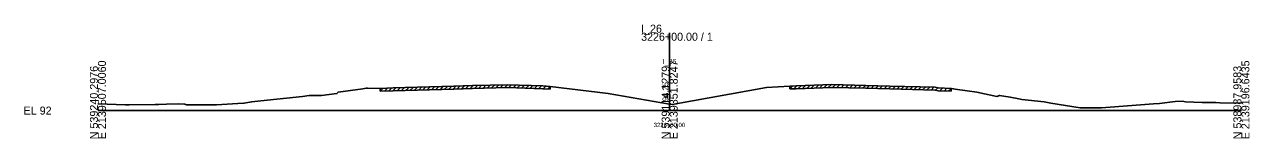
# Model space of a CAD drawing. Extents: x -13101 to 4803, y -924 to 22390.
# Drawn here: x 1974.3 to 2402.8, y 12990.3 to 13030 of the extents above; entities that cross this region are included whole.
import ezdxf

# ---------------------------------------------------------------- set-up
doc = ezdxf.new("R2010")
doc.units = 0
for name, color, linetype in [('RD_GPK_XS_Cell', 7, 'Continuous'), ('RD_XS_ExGround', 7, 'Continuous'), ('RD_XS_ExPaveRet', 7, 'Continuous'), ('RD_XS_TX_Baseline', 7, 'Continuous'), ('RD_XS_TX_Elev_EX', 7, 'Continuous'), ('RD_XS_TX_Station', 7, 'Continuous')]:
    doc.layers.add(name, color=color, linetype=linetype)

msp = doc.modelspace()

# ---------------------------------------------------------------- linework, layer by layer
at = {"layer": 'RD_GPK_XS_Cell'}
for p, q in [((2200, 13000), (2200, 13027.15)), ((2000, 13000), (2200, 13000)), ((2200, 13000), (2400, 13000))]:
    msp.add_line(p, q, dxfattribs=at)
at = {"layer": 'RD_XS_ExGround'}
msp.add_lwpolyline([(2000, 13002.32), (2009.65, 13002.05), (2010.92, 13002.01), (2020.04, 13002.16), (2020.93, 13002.16), (2021.28, 13002.17), (2024, 13002.29), (2028.09, 13002.33), (2030.37, 13002.27), (2030.93, 13002.04), (2031.49, 13002.03), (2040.94, 13002.07), (2041.47, 13002.06), (2048.99, 13002.46), (2051.05, 13002.58), (2053.82, 13003.06), (2056.98, 13003.41), (2071.61, 13004.96), (2073.84, 13005.24), (2076.21, 13005.22), (2078.21, 13005.25), (2083.62, 13005.96), (2083.99, 13006.45), (2092.65, 13007.57), (2093.86, 13007.82), (2094.26, 13007.81), (2098.71, 13007.75), (2103.22, 13007.9), (2124.54, 13008.53), (2131, 13008.75), (2143.23, 13009.02), (2155.69, 13008.62), (2158.15, 13008.46), (2178.43, 13006.02), (2200, 13002.25), (2200.9, 13002.1), (2233.82, 13008.05), (2241.98, 13008.54), (2244.21, 13008.63), (2256.7, 13009.05), (2268.68, 13008.78), (2277.02, 13008.54), (2292.83, 13008.13), (2293.92, 13007.89), (2298.53, 13007.74), (2299.19, 13007.63), (2299.88, 13007.51), (2304.06, 13006.85), (2307.51, 13006.38), (2314.48, 13004.97), (2315.4, 13005.32), (2319.09, 13004.65), (2322.18, 13004.05), (2322.74, 13003.95), (2323.14, 13003.9), (2331.05, 13003.05), (2333.39, 13002.6), (2343.61, 13001.02), (2345.05, 13001.01), (2351.06, 13000.99), (2369.27, 13002.32), (2371.33, 13002.48), (2376.84, 13003.18), (2379.31, 13003.29), (2380.48, 13003.08), (2386.33, 13002.87), (2391.08, 13002.77), (2392.48, 13002.68), (2400, 13002.59)], dxfattribs=at)
at = {"layer": 'RD_XS_ExPaveRet'}
for p, q in [((2098.71, 13006.75), (2099.74, 13007.79)), ((2098.71, 13006.75), (2098.71, 13007.75)), ((2098.71, 13006.75), (2103.22, 13006.9)), ((2100.21, 13006.8), (2101.24, 13007.83)), ((2101.71, 13006.85), (2102.74, 13007.88)), ((2103.21, 13006.9), (2104.24, 13007.93)), ((2103.22, 13006.9), (2124.54, 13007.53)), ((2104.71, 13006.94), (2105.74, 13007.97)), ((2106.21, 13006.99), (2107.24, 13008.02)), ((2107.71, 13007.03), (2108.74, 13008.06)), ((2109.21, 13007.07), (2110.24, 13008.11)), ((2110.71, 13007.12), (2111.74, 13008.15)), ((2112.21, 13007.16), (2113.24, 13008.19)), ((2113.71, 13007.21), (2114.74, 13008.24)), ((2115.21, 13007.25), (2116.24, 13008.28)), ((2116.71, 13007.3), (2117.74, 13008.33)), ((2118.21, 13007.34), (2119.24, 13008.37)), ((2119.71, 13007.38), (2120.74, 13008.41)), ((2121.21, 13007.43), (2122.24, 13008.46)), ((2122.71, 13007.47), (2123.74, 13008.5)), ((2124.21, 13007.52), (2125.24, 13008.55)), ((2124.54, 13007.53), (2131, 13007.75)), ((2125.71, 13007.57), (2126.74, 13008.6)), ((2127.21, 13007.62), (2128.24, 13008.65)), ((2128.71, 13007.67), (2129.74, 13008.7)), ((2130.21, 13007.72), (2131.24, 13008.75)), ((2131, 13007.75), (2143.23, 13008.02)), ((2131.71, 13007.76), (2132.73, 13008.79)), ((2133.21, 13007.8), (2134.23, 13008.82)), ((2134.71, 13007.83), (2135.73, 13008.85)), ((2136.21, 13007.86), (2137.23, 13008.88)), ((2137.71, 13007.89), (2138.73, 13008.92)), ((2139.21, 13007.93), (2140.23, 13008.95)), ((2140.71, 13007.96), (2141.73, 13008.98)), ((2142.21, 13007.99), (2143.23, 13009.02)), ((2143.23, 13008.02), (2155.69, 13007.62)), ((2143.71, 13008), (2144.68, 13008.97)), ((2145.21, 13007.95), (2146.18, 13008.92)), ((2146.71, 13007.91), (2147.68, 13008.88)), ((2148.21, 13007.86), (2149.18, 13008.83)), ((2149.71, 13007.81), (2150.68, 13008.78)), ((2151.21, 13007.77), (2152.18, 13008.73)), ((2152.71, 13007.72), (2153.68, 13008.69)), ((2154.21, 13007.67), (2155.18, 13008.64)), ((2155.69, 13007.62), (2158.15, 13007.46)), ((2155.71, 13007.62), (2156.64, 13008.56)), ((2157.21, 13007.52), (2158.14, 13008.46)), ((2158.15, 13008.46), (2158.15, 13007.46)), ((2241.98, 13007.54), (2243.03, 13008.58)), ((2241.98, 13007.54), (2241.98, 13008.54)), ((2241.98, 13007.54), (2244.21, 13007.63)), ((2243.48, 13007.6), (2244.53, 13008.65)), ((2244.21, 13007.63), (2256.7, 13008.05)), ((2244.98, 13007.66), (2246.02, 13008.69)), ((2246.48, 13007.71), (2247.52, 13008.74)), ((2247.98, 13007.76), (2249.02, 13008.79)), ((2249.48, 13007.81), (2250.52, 13008.84)), ((2250.98, 13007.86), (2252.02, 13008.89)), ((2252.48, 13007.91), (2253.52, 13008.94)), ((2253.98, 13007.96), (2255.02, 13008.99)), ((2255.48, 13008.01), (2256.52, 13009.04)), ((2256.7, 13008.05), (2268.68, 13007.78)), ((2256.98, 13008.04), (2257.96, 13009.02)), ((2258.48, 13008.01), (2259.46, 13008.99)), ((2259.98, 13007.98), (2260.96, 13008.95)), ((2261.48, 13007.94), (2262.46, 13008.92)), ((2262.98, 13007.91), (2263.96, 13008.89)), ((2264.48, 13007.88), (2265.46, 13008.85)), ((2265.98, 13007.84), (2266.96, 13008.82)), ((2267.48, 13007.81), (2268.46, 13008.79)), ((2268.68, 13007.78), (2277.02, 13007.54)), ((2268.98, 13007.77), (2269.96, 13008.75)), ((2270.48, 13007.73), (2271.46, 13008.7)), ((2271.98, 13007.69), (2272.96, 13008.66)), ((2273.48, 13007.65), (2274.46, 13008.62)), ((2274.98, 13007.6), (2275.96, 13008.57)), ((2276.48, 13007.56), (2277.46, 13008.53)), ((2277.02, 13007.54), (2292.83, 13007.13)), ((2277.98, 13007.52), (2278.96, 13008.49)), ((2279.48, 13007.48), (2280.46, 13008.46)), ((2280.98, 13007.44), (2281.96, 13008.42)), ((2282.48, 13007.4), (2283.46, 13008.38)), ((2283.98, 13007.36), (2284.96, 13008.34)), ((2285.48, 13007.33), (2286.46, 13008.3)), ((2286.98, 13007.29), (2287.96, 13008.26)), ((2288.48, 13007.25), (2289.46, 13008.22)), ((2289.98, 13007.21), (2290.96, 13008.18)), ((2291.48, 13007.17), (2292.46, 13008.14)), ((2292.83, 13007.13), (2293.92, 13006.89)), ((2292.98, 13007.1), (2293.8, 13007.92)), ((2293.92, 13006.89), (2298.53, 13006.74)), ((2294.48, 13006.87), (2295.45, 13007.84)), ((2295.98, 13006.82), (2296.95, 13007.79)), ((2297.48, 13006.77), (2298.45, 13007.74)), ((2298.53, 13007.74), (2298.53, 13006.74))]:
    msp.add_line(p, q, dxfattribs=at)

# ---------------------------------------------------------------- texts
at = {"layer": 'RD_GPK_XS_Cell'}
for s, p in [('I_26', (2190, 13027.15)), ('3226+00.00 / 1', (2190, 13024.35)), ('EL 92', (1974, 12998.6))]:
    msp.add_text(s, height=2.8, dxfattribs=at).set_placement(p)
for s, p in [('N 539240.2976', (2000, 12990)), ('E 2139507.0060', (2002.8, 12990)), ('N 539114.1279', (2200, 12990)), ('E 2139351.8247', (2202.8, 12990)), ('N 538987.9583', (2400, 12990)), ('E 2139196.6435', (2402.8, 12990))]:
    msp.add_text(s, height=2.8, rotation=90, dxfattribs=at).set_placement(p)
at = {"layer": 'RD_XS_TX_Baseline'}
msp.add_text('I_26', height=1.75, dxfattribs=at).set_placement((2197.6, 13016.25))
at = {"layer": 'RD_XS_TX_Elev_EX'}
msp.add_text('94.25', height=2, rotation=90, dxfattribs=at).set_placement((2199.5, 13003.25))
at = {"layer": 'RD_XS_TX_Station'}
msp.add_text('3226+00.00', height=1.5, dxfattribs=at).set_placement((2194.41, 12994.25))

doc.saveas('drawing.dxf')
